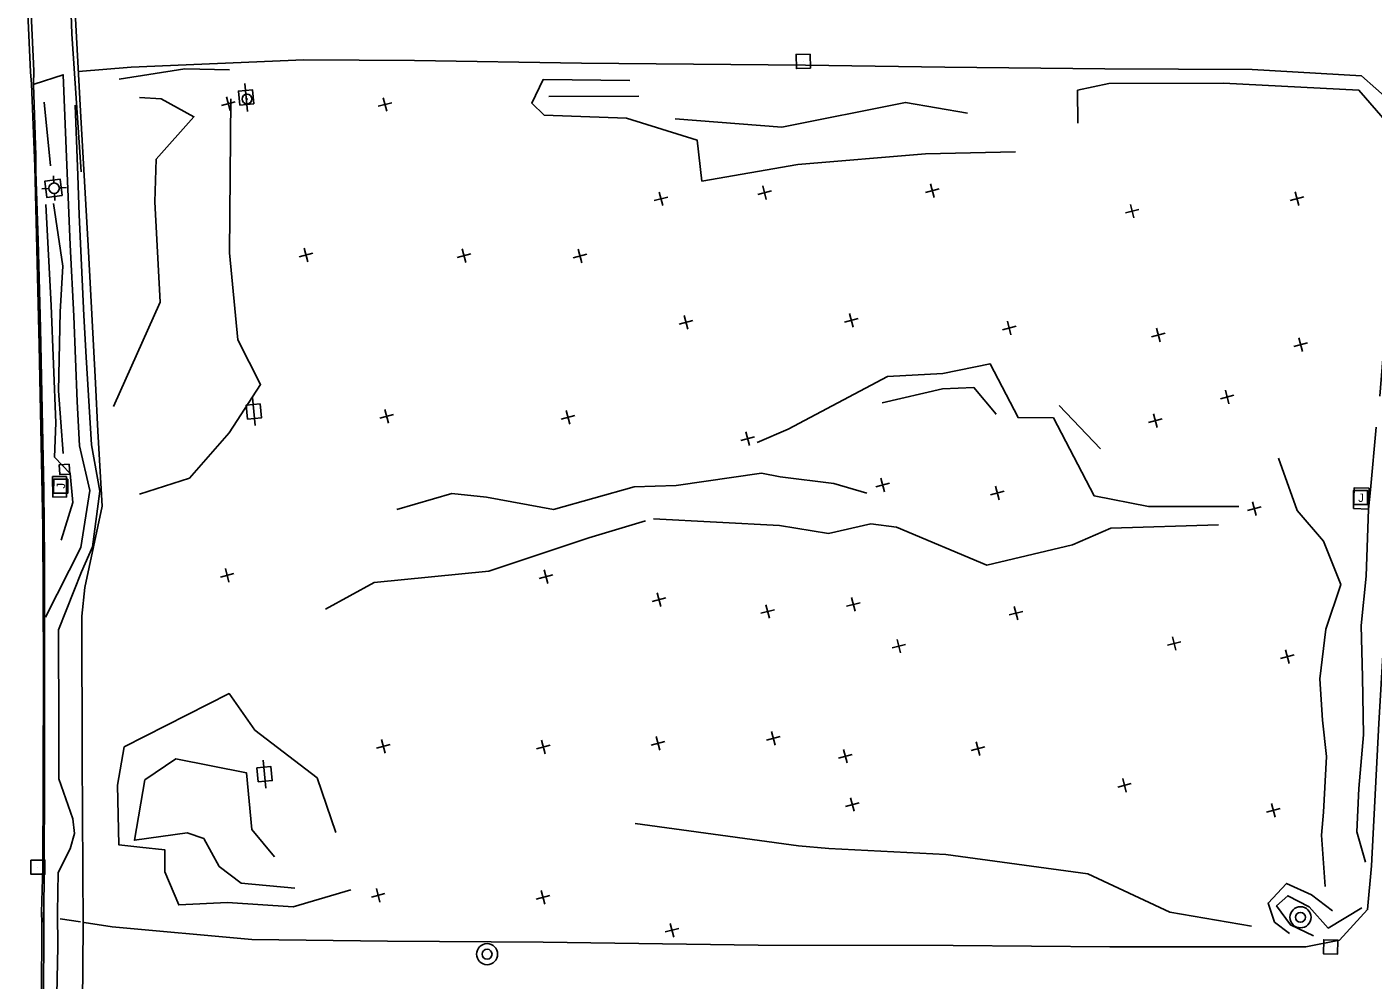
# Model space of a CAD drawing. Extents: x 4711259 to 4716401, y 890074 to 892728.
# Drawn here: x 4712107.6 to 4712586.5, y 891570.9 to 891909.7 of the extents above; entities that cross this region are included whole.
import ezdxf

# ---------------------------------------------------------------- set-up
doc = ezdxf.new("R2010")
doc.units = 0
for name, color, linetype in [('E_HY_STORM_Inlet', 7, 'Continuous'), ('E_HY_STORM_MH', 7, 'Continuous'), ('E_RDWY_ROAD_Curb', 7, 'Continuous'), ('E_RDWY_ROAD_EdgeAsph', 7, 'Continuous'), ('E_RDWY_ROAD_EdgeConc', 7, 'Continuous'), ('E_RDWY_ROAD_Fence', 7, 'Continuous'), ('E_RDWY_ROAD_Sidewalk', 7, 'Continuous'), ('E_RDWY_ROAD_TBofCurb', 7, 'Continuous'), ('E_TERR_DTM_BrkLines', 7, 'Continuous'), ('E_TERR_DTM_RandomPt', 7, 'Continuous'), ('E_UTIL_COMM_General', 7, 'Continuous'), ('E_UTIL_ELEC_GENERAL', 7, 'Continuous'), ('E_UTIL_ELEC_POLE', 7, 'Continuous'), ('E_UTIL_MISC_General', 7, 'Continuous'), ('E_UTIL_WTR_General', 7, 'Continuous')]:
    doc.layers.add(name, color=color, linetype=linetype)

msp = doc.modelspace()

# ---------------------------------------------------------------- linework, layer by layer
at = {"layer": 'E_HY_STORM_Inlet'}
for p, q in [((4712383.8, 891897.45), (4712383.8, 891897.45)), ((4712111.55, 891610.99), (4712111.55, 891610.99)), ((4712571.38, 891582.61), (4712571.38, 891582.61))]:
    msp.add_line(p, q, dxfattribs=at)
for points in [[(4712386.23, 891900.02), (4712386.36, 891895.02), (4712381.37, 891894.89), (4712381.23, 891899.89)], [(4712109.06, 891613.5), (4712114.06, 891613.48), (4712114.03, 891608.48), (4712109.03, 891608.5)], [(4712573.93, 891585.07), (4712573.84, 891580.07), (4712568.84, 891580.16), (4712568.93, 891585.16)]]:
    msp.add_lwpolyline(points, close=True, dxfattribs=at)
at = {"layer": 'E_HY_STORM_MH'}
for centre, radius in [((4712560.65, 891593.16), 3.75), ((4712560.65, 891593.16), 1.76), ((4712271.33, 891580.05), 3.75), ((4712271.33, 891580.05), 1.76)]:
    msp.add_circle(centre, radius, dxfattribs=at)
at = {"layer": 'E_RDWY_ROAD_Curb'}
msp.add_lwpolyline([(4712128.26, 891381.39), (4712125.55, 891383.03), (4712121.64, 891386.33), (4712115.83, 891393.82), (4712113.87, 891398.54), (4712113.04, 891402.77), (4712112.33, 891411.88), (4712112.37, 891453.3), (4712112.58, 891509.08), (4712112.73, 891556.54), (4712112.81, 891563.66), (4712113, 891591.26), (4712112.87, 891594.89), (4712113.25, 891611.03), (4712113.37, 891640.66), (4712113.52, 891682.17), (4712113.29, 891731.86), (4712112.03, 891796.52), (4712110.46, 891860.01), (4712109.29, 891889.41), (4712108.95, 891893.59), (4712107.64, 891922.46)], dxfattribs=at)
at = {"layer": 'E_RDWY_ROAD_EdgeAsph'}
for points in [[(4712126.02, 891893.8), (4712144.73, 891895.36), (4712206.15, 891897.97), (4712245.53, 891897.79)], [(4712304.96, 891896.85), (4712245.53, 891897.79)], [(4712304.96, 891896.85), (4712384.63, 891896.03), (4712434.12, 891895.34), (4712491.07, 891894.75), (4712543.41, 891894.49), (4712582.4, 891892.24), (4712597.63, 891878.83), (4712597.65, 891831.39), (4712594.45, 891776.63), (4712591.79, 891718.65), (4712588.49, 891662.05), (4712585.87, 891611.48), (4712584.5, 891595.88), (4712574.49, 891585.03), (4712562.61, 891582.71), (4712492.86, 891582.66), (4712437.1, 891583.09), (4712367.74, 891583.27), (4712291.22, 891584.33)], [(4712119.5, 891592.61), (4712126.67, 891591.52)], [(4712128.02, 891591.31), (4712137.99, 891589.78), (4712187.67, 891585.32), (4712235.95, 891584.72), (4712291.22, 891584.33)]]:
    msp.add_lwpolyline(points, dxfattribs=at)
at = {"layer": 'E_RDWY_ROAD_EdgeConc'}
for points in [[(4712120.17, 891849.7), (4712114.72, 891849.08), (4712114.05, 891854.88), (4712119.5, 891855.5)], [(4712116.8, 891742.56), (4712116.78, 891749.85), (4712121.7, 891749.86), (4712121.72, 891742.58)], [(4712579.5, 891738.49), (4712584.8, 891738.29), (4712585.07, 891745.7), (4712579.77, 891745.89)]]:
    msp.add_lwpolyline(points, close=True, dxfattribs=at)
at = {"layer": 'E_RDWY_ROAD_Fence'}
msp.add_lwpolyline([(4712128.59, 891451.64), (4712127.77, 891481.95), (4712127.92, 891531.97), (4712127.41, 891562.39), (4712127.6, 891590.09), (4712127.3, 891649.86), (4712127.17, 891700.22), (4712128.2, 891710.35), (4712134.44, 891739.35), (4712132.91, 891765.97), (4712132.02, 891783.01), (4712129.51, 891829.8), (4712126.66, 891879.73), (4712124.56, 891919.3), (4712121.22, 891968.8), (4712118.38, 892019.02), (4712115.97, 892060.36), (4712113.52, 892109.62), (4712110.82, 892170.44), (4712108.89, 892208.75)], dxfattribs=at)
at = {"layer": 'E_RDWY_ROAD_Sidewalk'}
for points in [[(4712126.93, 891858.21), (4712124.51, 891893.18), (4712123.61, 891907.21), (4712123.16, 891921.16), (4712121.14, 891935.44)], [(4712110.21, 891889.3), (4712120.58, 891892.68), (4712121.8, 891860.48)], [(4712118.88, 891695.33), (4712127.05, 891716.03), (4712130.94, 891724.85), (4712133.57, 891744.59), (4712130.63, 891761.15), (4712128.76, 891792.3), (4712127.92, 891807.15), (4712126.25, 891842.87), (4712125.79, 891856.85), (4712124.86, 891881.83)], [(4712121.8, 891860.48), (4712123.01, 891832.21), (4712124.32, 891806.9), (4712125.49, 891776.51), (4712126.3, 891760.72), (4712129.98, 891744.92), (4712126.86, 891724.68), (4712114.23, 891699.91)], [(4712118.88, 891695.33), (4712118.95, 891660.37), (4712118.95, 891642.42), (4712123.96, 891628.2), (4712124.58, 891622.91), (4712123, 891617.48), (4712118.71, 891609.04), (4712118.53, 891594.89), (4712118.62, 891582.72), (4712118.2, 891560.08), (4712118.39, 891554.48), (4712118.03, 891534.35), (4712118.11, 891510.21), (4712117.8, 891471.09), (4712117.51, 891438.4), (4712117.47, 891412.49), (4712118.02, 891407.07)]]:
    msp.add_lwpolyline(points, dxfattribs=at)
at = {"layer": 'E_RDWY_ROAD_TBofCurb'}
for p, q in [((4712110.81, 891858.26), (4712111.62, 891833.79)), ((4712111.62, 891833.74), (4712112.42, 891802.6)), ((4712112.42, 891802.6), (4712113.09, 891773.57)), ((4712113.09, 891773.57), (4712113.64, 891745.1)), ((4712113.64, 891745.1), (4712113.95, 891720.31)), ((4712113.95, 891720.31), (4712113.92, 891700.7)), ((4712113.56, 891594.93), (4712113.54, 891591.47))]:
    msp.add_line(p, q, dxfattribs=at)
for points in [[(4712110.81, 891858.26), (4712110.79, 891863.98), (4712110, 891889.17), (4712110.1, 891894.08), (4712108.88, 891919.59)], [(4712110.81, 891858.26), (4712112.23, 891806.23), (4712113.41, 891752.41), (4712113.86, 891699.59), (4712113.9, 891642.74), (4712113.8, 891609.38), (4712113.63, 891594.74), (4712113.61, 891591.26), (4712113.53, 891562.3), (4712113.49, 891555.88), (4712113.15, 891510.23), (4712112.99, 891461.79), (4712112.75, 891412.45), (4712113.54, 891402.88), (4712114.41, 891399.12), (4712116.39, 891394.09), (4712121.95, 891386.8), (4712125.93, 891383.52), (4712128.52, 891381.7)]]:
    msp.add_lwpolyline(points, dxfattribs=at)
at = {"layer": 'E_TERR_DTM_BrkLines'}
for points in [[(4712140.41, 891891.14), (4712163.85, 891894.78), (4712179.66, 891894.41)], [(4712320.95, 891877.25), (4712291.66, 891878.27), (4712287.19, 891882.53), (4712291.24, 891890.95), (4712322.05, 891890.63)], [(4712588.91, 891778.44), (4712592.04, 891818.18), (4712593.13, 891848.88), (4712591.62, 891875.44), (4712581.43, 891887.14), (4712533.27, 891889.67), (4712492.53, 891889.57), (4712481.34, 891887.18), (4712481.48, 891875.5)], [(4712116.04, 891860.32), (4712113.83, 891882.96)], [(4712138.46, 891774.7), (4712155.06, 891811.88), (4712153.16, 891847.51), (4712153.66, 891862.66), (4712167.07, 891877.72), (4712155.45, 891884.12), (4712147.66, 891884.57)], [(4712180.22, 891884.13), (4712179.68, 891829.33), (4712182.69, 891798.47), (4712190.76, 891782.62), (4712179.54, 891765.39), (4712165.43, 891749.26), (4712147.69, 891743.62)], [(4712293.26, 891884.96), (4712325.35, 891885.01)], [(4712338.24, 891877.04), (4712376.19, 891874.06), (4712420.21, 891882.83), (4712442.16, 891879.05)], [(4712459.25, 891865.33), (4712427.27, 891864.58), (4712381.88, 891860.75), (4712347.71, 891854.89), (4712346.07, 891869.37), (4712320.95, 891877.25)], [(4712120.58, 891758.08), (4712118.83, 891780.31), (4712119.47, 891808.43), (4712120.4, 891824.61), (4712117.07, 891846.89)], [(4712114.38, 891846.52), (4712116.28, 891810.66), (4712117.93, 891768.97), (4712117.44, 891756.79), (4712123.04, 891750.98), (4712124, 891740.62), (4712119.79, 891727.17)], [(4712538.69, 891739.25), (4712506.63, 891739.17), (4712487.26, 891743.02), (4712472.77, 891770.77), (4712460.17, 891770.81), (4712450.21, 891789.96), (4712433.4, 891786.53), (4712413.76, 891785.36), (4712378.43, 891766.7), (4712367.37, 891761.9)], [(4712411.9, 891776.02), (4712433.34, 891781), (4712444.5, 891781.47), (4712452.39, 891772.01), (4712452.41, 891772.01)], [(4712489.5, 891759.69), (4712474.76, 891775.11)], [(4712587.58, 891767.34), (4712585.52, 891745.07), (4712584.8, 891738.29), (4712584.06, 891714.42), (4712582.23, 891696.91), (4712582.69, 891678.56), (4712583.02, 891658.08), (4712581.39, 891638.94), (4712580.64, 891623.52), (4712583.73, 891612.8)], [(4712569.39, 891604.17), (4712568.11, 891622.36), (4712568.89, 891630.52), (4712569.93, 891650.34), (4712568.5, 891663.24), (4712567.51, 891677.92), (4712569.69, 891695.62), (4712575.03, 891711.52), (4712568.86, 891726.87), (4712559.47, 891737.79), (4712552.81, 891756.37)], [(4712323.6, 891746.22), (4712338.52, 891746.61), (4712368.89, 891751.04)], [(4712368.89, 891751.04), (4712375.63, 891749.77), (4712394.68, 891747.38), (4712406.42, 891743.97)], [(4712239.2, 891738.08), (4712258.77, 891743.77), (4712271.17, 891742.5), (4712294.99, 891738.11), (4712323.6, 891746.22)], [(4712327.63, 891734.09), (4712307.48, 891728.08), (4712271.89, 891716.15), (4712231.11, 891712.18), (4712213.8, 891702.69)], [(4712330.5, 891734.86), (4712375.32, 891732.44), (4712392.76, 891729.56), (4712407.86, 891733.09), (4712417.01, 891731.87), (4712449.11, 891718.37), (4712479.51, 891725.62), (4712493.22, 891731.48), (4712531.5, 891732.65)], [(4712222.88, 891602.88), (4712202.34, 891596.88), (4712179.02, 891598.37), (4712161.64, 891597.59), (4712156.7, 891609.27), (4712156.66, 891617.16), (4712147.76, 891618.07), (4712140.3, 891618.93), (4712139.84, 891640.16), (4712142.25, 891653.71), (4712179.56, 891672.72), (4712188.75, 891659.63), (4712210.86, 891642.72), (4712217.53, 891623.31)], [(4712202.89, 891603.5), (4712183.86, 891605.29), (4712176.05, 891611.28), (4712170.55, 891621.23), (4712164.67, 891623.15), (4712145.9, 891620.53), (4712149.62, 891641.99), (4712160.56, 891649.5), (4712185.79, 891644.5), (4712187.69, 891624.4), (4712195.76, 891614.68)], [(4712324.01, 891626.52), (4712382.04, 891618.62), (4712392.86, 891617.65), (4712434.48, 891615.44), (4712485.03, 891608.63), (4712514.14, 891594.98), (4712543.28, 891590.06)], [(4712572, 891595.42), (4712564.51, 891601.15), (4712555.73, 891605.23), (4712549.15, 891598.24), (4712551.46, 891591.46), (4712556.79, 891587.37)], [(4712565.27, 891586.58), (4712557.04, 891590.52), (4712552.17, 891597.25), (4712556.14, 891600.81), (4712563.71, 891596.94), (4712570.44, 891589.34), (4712582.47, 891596.49)]]:
    msp.add_lwpolyline(points, dxfattribs=at)
at = {"layer": 'E_TERR_DTM_RandomPt'}
for p, q in [((4712176.83, 891881.73), (4712181.67, 891883.01)), ((4712179.88, 891879.95), (4712178.61, 891884.79)), ((4712232.61, 891881.47), (4712237.45, 891882.74)), ((4712235.67, 891879.68), (4712234.4, 891884.52)), ((4712370.65, 891848.34), (4712369.37, 891853.17)), ((4712427.3, 891850.8), (4712432.14, 891852.07)), ((4712430.36, 891849.02), (4712429.08, 891853.85)), ((4712330.81, 891847.93), (4712335.65, 891849.21)), ((4712333.87, 891846.15), (4712332.59, 891850.99)), ((4712367.59, 891850.12), (4712372.43, 891851.39)), ((4712556.99, 891848.01), (4712561.83, 891849.28)), ((4712560.05, 891846.22), (4712558.78, 891851.06)), ((4712498.35, 891843.54), (4712503.19, 891844.82)), ((4712501.41, 891841.76), (4712500.14, 891846.6)), ((4712204.51, 891828), (4712209.34, 891829.27)), ((4712207.56, 891826.22), (4712206.29, 891831.05)), ((4712260.67, 891827.72), (4712265.5, 891829)), ((4712263.72, 891825.94), (4712262.45, 891830.78)), ((4712301.95, 891827.58), (4712306.78, 891828.85)), ((4712305, 891825.79), (4712303.73, 891830.63)), ((4712339.66, 891804.06), (4712344.49, 891805.33)), ((4712342.71, 891802.28), (4712341.44, 891807.11)), ((4712398.48, 891804.77), (4712403.32, 891806.04)), ((4712401.53, 891802.99), (4712400.26, 891807.82)), ((4712457.67, 891800.26), (4712456.4, 891805.1)), ((4712454.62, 891802.05), (4712459.46, 891803.32)), ((4712507.7, 891799.52), (4712512.54, 891800.79)), ((4712510.76, 891797.74), (4712509.48, 891802.58)), ((4712561.35, 891794.29), (4712560.08, 891799.13)), ((4712558.3, 891796.08), (4712563.14, 891797.35)), ((4712535.22, 891775.73), (4712533.92, 891780.56)), ((4712532.16, 891777.5), (4712536.99, 891778.79)), ((4712233.15, 891770.59), (4712237.98, 891771.86)), ((4712236.2, 891768.81), (4712234.93, 891773.65)), ((4712297.7, 891770.29), (4712302.54, 891771.56)), ((4712300.76, 891768.51), (4712299.49, 891773.34)), ((4712506.64, 891769.03), (4712511.47, 891770.33)), ((4712509.7, 891767.27), (4712508.41, 891772.1)), ((4712364.66, 891760.91), (4712363.39, 891765.74)), ((4712361.61, 891762.69), (4712366.44, 891763.96)), ((4712409.64, 891746.2), (4712414.48, 891747.47)), ((4712412.7, 891744.42), (4712411.43, 891749.26)), ((4712453.47, 891741.61), (4712452.2, 891746.45)), ((4712450.42, 891743.4), (4712455.25, 891744.67)), ((4712541.85, 891737.77), (4712546.69, 891739.04)), ((4712544.91, 891735.99), (4712543.64, 891740.82)), ((4712176.45, 891714.06), (4712181.29, 891715.33)), ((4712179.5, 891712.28), (4712178.23, 891717.12)), ((4712289.88, 891713.66), (4712294.72, 891714.93)), ((4712292.94, 891711.88), (4712291.67, 891716.71)), ((4712333.11, 891703.65), (4712331.84, 891708.49)), ((4712330.06, 891705.43), (4712334.89, 891706.7)), ((4712371.77, 891699.46), (4712370.48, 891704.29)), ((4712399.2, 891703.74), (4712404.04, 891705.01)), ((4712402.25, 891701.96), (4712400.98, 891706.8)), ((4712460.13, 891698.86), (4712458.86, 891703.69)), ((4712368.71, 891701.23), (4712373.54, 891702.52)), ((4712457.07, 891700.64), (4712461.91, 891701.91)), ((4712415.37, 891688.9), (4712420.2, 891690.19)), ((4712418.43, 891687.13), (4712417.14, 891691.96)), ((4712513.29, 891689.86), (4712518.13, 891691.13)), ((4712516.34, 891688.08), (4712515.07, 891692.91)), ((4712553.56, 891685.15), (4712558.39, 891686.42)), ((4712556.61, 891683.36), (4712555.34, 891688.2)), ((4712235.06, 891651.53), (4712233.78, 891656.36)), ((4712291.99, 891651.25), (4712290.72, 891656.09)), ((4712329.73, 891654.4), (4712334.57, 891655.67)), ((4712332.78, 891652.62), (4712331.51, 891657.45)), ((4712370.75, 891656.16), (4712375.58, 891657.43)), ((4712373.8, 891654.37), (4712372.53, 891659.21)), ((4712446.59, 891650.67), (4712445.32, 891655.51)), ((4712232, 891653.31), (4712236.84, 891654.58)), ((4712288.94, 891653.04), (4712293.77, 891654.31)), ((4712396.36, 891649.79), (4712401.19, 891651.08)), ((4712399.43, 891648.02), (4712398.13, 891652.85)), ((4712443.54, 891652.45), (4712448.37, 891653.72)), ((4712498.7, 891637.67), (4712497.43, 891642.51)), ((4712495.64, 891639.45), (4712500.48, 891640.72)), ((4712398.79, 891632.6), (4712403.62, 891633.9)), ((4712401.85, 891630.84), (4712400.55, 891635.67)), ((4712548.58, 891630.56), (4712553.42, 891631.83)), ((4712551.63, 891628.78), (4712550.36, 891633.61)), ((4712233.21, 891598.52), (4712231.94, 891603.36)), ((4712291.88, 891597.87), (4712290.61, 891602.71)), ((4712230.15, 891600.31), (4712234.99, 891601.58)), ((4712288.82, 891599.66), (4712293.66, 891600.93)), ((4712334.64, 891587.94), (4712339.47, 891589.21)), ((4712337.69, 891586.15), (4712336.42, 891590.99))]:
    msp.add_line(p, q, dxfattribs=at)
at = {"layer": 'E_UTIL_COMM_General'}
msp.add_lwpolyline([(4712122.85, 891750.74), (4712119.36, 891750.53), (4712119.15, 891754.03), (4712122.65, 891754.24)], close=True, dxfattribs=at)
at = {"layer": 'E_UTIL_ELEC_GENERAL'}
for points in [[(4712122.16, 891748.89), (4712122.14, 891743.89), (4712117.14, 891743.91), (4712117.16, 891748.91)], [(4712584.51, 891739.87), (4712579.51, 891739.89), (4712579.53, 891744.89), (4712584.53, 891744.87)]]:
    msp.add_lwpolyline(points, close=True, dxfattribs=at)
at = {"layer": 'E_UTIL_ELEC_POLE'}
for p, q in [((4712186.09, 891879.65), (4712185.13, 891889.61)), ((4712188.82, 891767.96), (4712187.87, 891777.92)), ((4712192.64, 891639.06), (4712191.69, 891649.02))]:
    msp.add_line(p, q, dxfattribs=at)
for points in [[(4712183.36, 891881.9), (4712182.88, 891886.88), (4712187.86, 891887.36), (4712188.34, 891882.38)], [(4712186.1, 891770.21), (4712185.62, 891775.19), (4712190.6, 891775.67), (4712191.07, 891770.69)], [(4712189.92, 891641.31), (4712189.44, 891646.29), (4712194.42, 891646.77), (4712194.89, 891641.79)]]:
    msp.add_lwpolyline(points, close=True, dxfattribs=at)
at = {"layer": 'E_UTIL_MISC_General'}
for p, q in [((4712185.78, 891884.07), (4712186.07, 891883.99)), ((4712185.88, 891883.88), (4712185.97, 891884.18))]:
    msp.add_line(p, q, dxfattribs=at)
msp.add_circle((4712185.95, 891884.04), 1.75, dxfattribs=at)
at = {"layer": 'E_UTIL_WTR_General'}
for p, q in [((4712117.22, 891854.21), (4712117.08, 891856.7)), ((4712115.45, 891852.23), (4712112.95, 891852.09)), ((4712119.19, 891852.44), (4712121.69, 891852.58)), ((4712117.43, 891850.46), (4712117.57, 891847.97))]:
    msp.add_line(p, q, dxfattribs=at)
msp.add_circle((4712117.32, 891852.34), 1.87, dxfattribs=at)

# ---------------------------------------------------------------- texts
at = {"layer": 'E_UTIL_ELEC_GENERAL'}
for rotation, p in [(89.7251, (4712121.22, 891745.55)), (359.7251, (4712581.16, 891740.81))]:
    msp.add_text('J', height=3, rotation=rotation, dxfattribs=at).set_placement(p)

doc.saveas('drawing.dxf')
